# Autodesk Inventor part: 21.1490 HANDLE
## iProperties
Created: 2012-03
Part Number: 21.1490 HANDLE
Document SubType Name: Modeling
Designer: Administrator
Density: 2.71 g/cm^3
Material: Aluminum-6061
Mass: 147.649 g
Surface Area: 118.5 cm^2
Volume: 54.483 cm^3
Author: Administrator
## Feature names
1. Base1
